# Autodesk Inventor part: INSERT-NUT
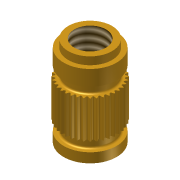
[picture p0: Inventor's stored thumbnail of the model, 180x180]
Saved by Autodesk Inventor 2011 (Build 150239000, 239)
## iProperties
Created: 2007-09
Part Number: INSERT-NUT
Material: Brass, Soft Yellow
Document SubType Name: Modeling
Density: 8.47 g/cm^3
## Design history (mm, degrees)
feature "Base1"
sketch "Sketch1"
  geometry: C1 r 1.859 at (0, 0) reference
extrude "Extrusion1" join sketch "Sketch1" distance "d0" = 9; taper "d1" = 0 deg
sketch "Sketch2"
  geometry: C1 r 2.275 at (0, 0) reference
hole "Hole1" sketch "Sketch2" at (0, 0) diameter "d2" = 3.302; stored, may be unused: countersink angle "d6" = 90 deg, drill point angle "d8" = 118 deg; dims "d3" = 6, "d4" = 4, "d5" = 2, "d7" = 8
body "Solid1"
